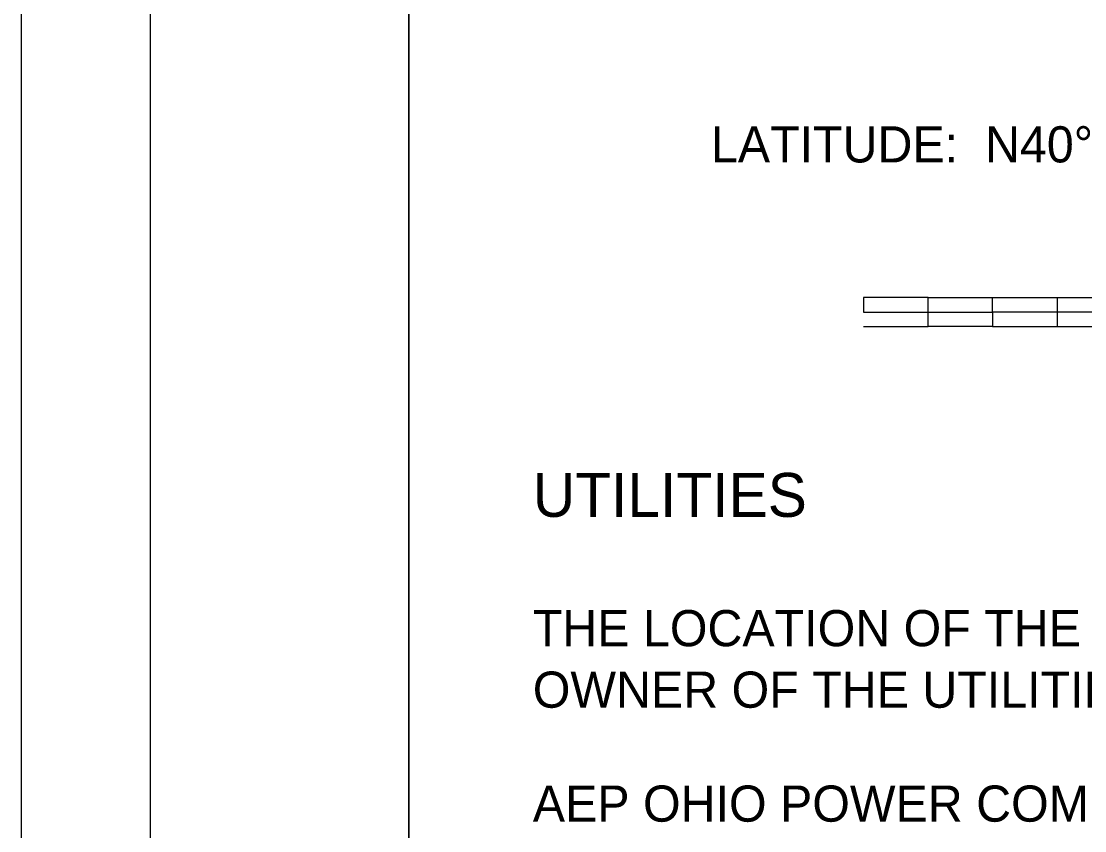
# Model space of a CAD drawing. Extents: x 0 to 34, y 0 to 22.
# Drawn here: x 0 to 4.117, y 11.083 to 14.216 of the extents above; entities that cross this region are included whole.
import ezdxf

# ---------------------------------------------------------------- set-up
doc = ezdxf.new("R2010")
doc.units = 0
for name, color, linetype in [('SH_Border', 7, 'Continuous'), ('SH_Cut_Line', 7, 'Continuous'), ('SH_Data', 7, 'Continuous'), ('SH_Text', 7, 'Continuous')]:
    doc.layers.add(name, color=color, linetype=linetype)

msp = doc.modelspace()

# ---------------------------------------------------------------- linework, layer by layer
at = {"layer": 'SH_Border'}
for points in [[(0.5, 21.5), (1.5, 21.5), (1.5, 0.5), (0.5, 0.5)], [(1.5, 21.5), (33.5, 21.5), (33.5, 0.5), (1.5, 0.5)]]:
    msp.add_lwpolyline(points, close=True, dxfattribs=at)
at = {"layer": 'SH_Cut_Line'}
msp.add_lwpolyline([(0, 0), (34, 0), (34, 22), (0, 22)], close=True, dxfattribs=at)
at = {"layer": 'SH_Data'}
for p, q in [((3.5102, 13.1466), (3.2602, 13.1466)), ((3.2602, 13.1466), (3.2602, 13.0904)), ((3.5102, 13.1466), (3.7602, 13.1466)), ((3.5102, 13.0904), (3.5102, 13.1466)), ((3.7602, 13.0904), (3.7602, 13.1466)), ((3.7602, 13.1466), (4.0102, 13.1466)), ((4.0102, 13.1466), (4.0102, 13.0904)), ((4.0102, 13.1466), (4.2602, 13.1466)), ((3.2602, 13.0904), (3.5102, 13.0904)), ((3.5102, 13.0904), (3.7602, 13.0904)), ((3.5102, 13.0341), (3.5102, 13.0904)), ((3.7602, 13.0904), (3.7602, 13.0341)), ((4.0102, 13.0904), (3.7602, 13.0904)), ((4.2602, 13.0904), (4.0102, 13.0904)), ((4.0102, 13.0904), (4.0102, 13.0341)), ((3.2602, 13.0341), (3.5102, 13.0341)), ((3.7602, 13.0341), (3.5102, 13.0341)), ((3.7602, 13.0341), (4.0102, 13.0341)), ((4.0102, 13.0341), (4.2602, 13.0341))]:
    msp.add_line(p, q, dxfattribs=at)

# ---------------------------------------------------------------- texts
msp.add_text('LATITUDE:  N40°38\'40"     LONGITUDE:  W82°12\'30"', height=0.14, dxfattribs=at).set_placement((2.6698, 13.6693))
at = {"layer": 'SH_Text'}
for s, height, p in [('UTILITIES', 0.17, (1.9802, 12.2974)), ('THE LOCATION OF THE UNDERGROUND UTILITIES SHOWN ON THE PLANS ARE OBTAINED FROM THE', 0.14, (1.9802, 11.7967)), ('OWNER OF THE UTILITIES AS REQUIRED BY SECTION 153.64 O.R.C.', 0.14, (1.9802, 11.5587)), ('AEP OHIO POWER COMPANY', 0.14, (1.9802, 11.1176))]:
    msp.add_text(s, height=height, dxfattribs=at).set_placement(p)

doc.saveas('drawing.dxf')
